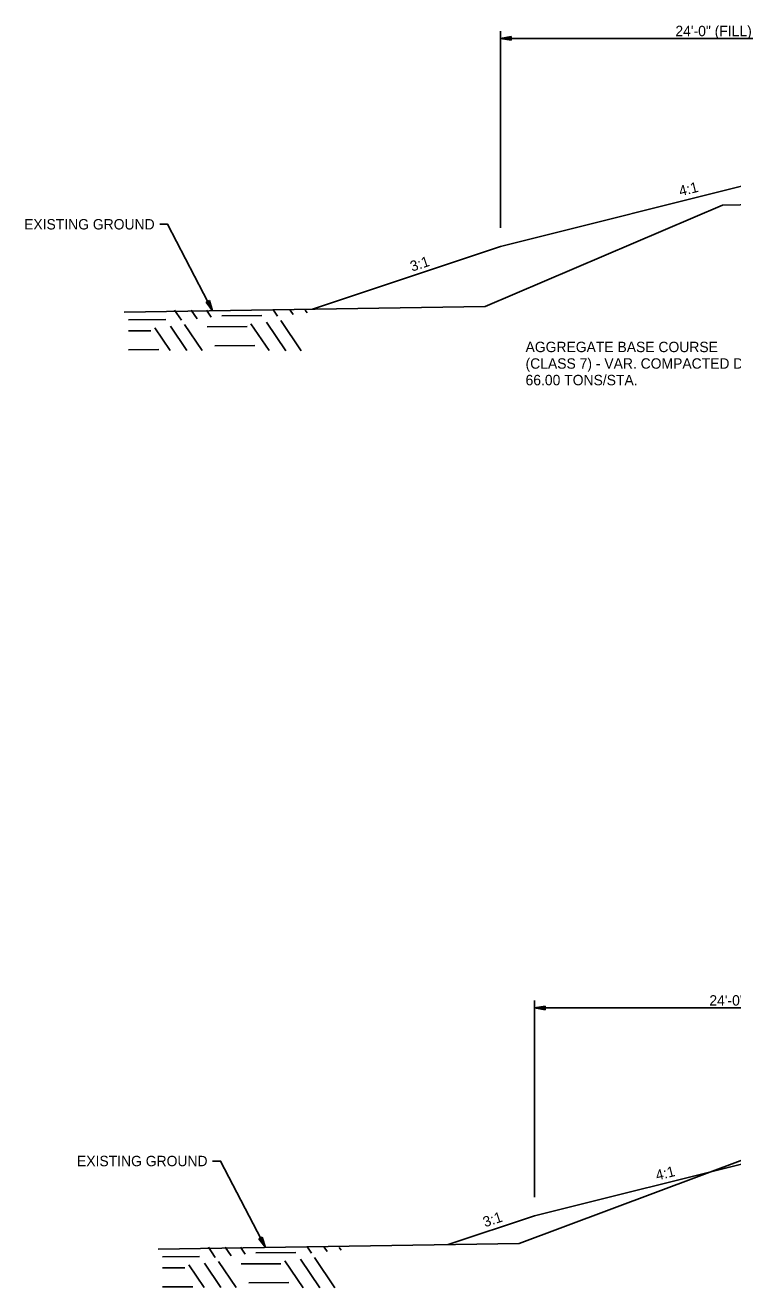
# Model space of a CAD drawing. Extents: x 1398183 to 1398373, y 1967240 to 1968889.
# Drawn here: x 1398185.5 to 1398225.6, y 1967722.3 to 1967793.9 of the extents above; entities that cross this region are included whole.
import ezdxf

# ---------------------------------------------------------------- set-up
doc = ezdxf.new("R2010")
doc.units = 0
for name, color, linetype in [('10', 7, 'Continuous'), ('19', 7, 'Continuous'), ('7', 7, 'Continuous'), ('9', 7, 'Continuous')]:
    doc.layers.add(name, color=color, linetype=linetype)

msp = doc.modelspace()

# ---------------------------------------------------------------- linework, layer by layer
at = {"layer": '19'}
for p, q in [((1398213.047, 1967793.262), (1398212.447, 1967793.157)), ((1398236.447, 1967793.157), (1398212.447, 1967793.157)), ((1398212.447, 1967793.157), (1398213.047, 1967793.052)), ((1398213.047, 1967793.207), (1398212.607, 1967793.172)), ((1398212.607, 1967793.142), (1398213.047, 1967793.102)), ((1398213.047, 1967793.052), (1398213.047, 1967793.262)), ((1398230.447, 1967785.854), (1398212.447, 1967781.354)), ((1398212.447, 1967781.354), (1398201.766, 1967777.793)), ((1398195.73, 1967778.19), (1398195.915, 1967778.286)), ((1398196.099, 1967777.706), (1398195.73, 1967778.19)), ((1398196.017, 1967777.842), (1398195.779, 1967778.211)), ((1398195.876, 1967778.262), (1398196.038, 1967777.856)), ((1398195.915, 1967778.286), (1398196.099, 1967777.706)), ((1398214.974, 1967738.244), (1398214.374, 1967738.139)), ((1398238.374, 1967738.139), (1398214.374, 1967738.139)), ((1398214.374, 1967738.139), (1398214.974, 1967738.034)), ((1398214.974, 1967738.189), (1398214.534, 1967738.154)), ((1398214.534, 1967738.124), (1398214.974, 1967738.084)), ((1398214.974, 1967738.034), (1398214.974, 1967738.244)), ((1398232.374, 1967730.836), (1398214.374, 1967726.336)), ((1398214.374, 1967726.336), (1398209.466, 1967724.7)), ((1398198.732, 1967725.025), (1398198.918, 1967725.121)), ((1398199.102, 1967724.541), (1398198.732, 1967725.025)), ((1398199.02, 1967724.677), (1398198.782, 1967725.045)), ((1398198.879, 1967725.097), (1398199.041, 1967724.691)), ((1398198.918, 1967725.121), (1398199.102, 1967724.541))]:
    msp.add_line(p, q, dxfattribs=at)
for points in [[(1398225.041, 1967783.694), (1398211.578, 1967777.944), (1398191.074, 1967777.629)], [(1398229.04, 1967783.774), (1398225.041, 1967783.694)], [(1398193.1, 1967782.612), (1398193.546, 1967782.612), (1398196.099, 1967777.706)], [(1398228.98, 1967730.552), (1398213.504, 1967724.762), (1398193.001, 1967724.447)], [(1398196.103, 1967729.447), (1398196.549, 1967729.447), (1398199.102, 1967724.541)]]:
    msp.add_lwpolyline(points, dxfattribs=at)
at = {"layer": '7'}
for p, q in [((1398212.447, 1967782.415), (1398212.447, 1967793.58)), ((1398214.374, 1967727.397), (1398214.373, 1967738.562))]:
    msp.add_line(p, q, dxfattribs=at)
at = {"layer": '9'}
for p, q in [((1398194.328, 1967777.162), (1398193.937, 1967777.743)), ((1398195.218, 1967777.253), (1398194.89, 1967777.741)), ((1398196.016, 1967777.344), (1398195.75, 1967777.74)), ((1398198.889, 1967777.432), (1398196.628, 1967777.418)), ((1398199.779, 1967777.394), (1398199.551, 1967777.733)), ((1398200.669, 1967777.485), (1398200.503, 1967777.732)), ((1398201.467, 1967777.576), (1398201.363, 1967777.73)), ((1398192.603, 1967776.571), (1398191.331, 1967776.563)), ((1398193.438, 1967777.201), (1398191.332, 1967777.187)), ((1398193.692, 1967775.449), (1398192.826, 1967776.738)), ((1398194.644, 1967775.447), (1398193.716, 1967776.829)), ((1398195.504, 1967775.446), (1398194.513, 1967776.92)), ((1398198.054, 1967776.803), (1398195.792, 1967776.788)), ((1398199.305, 1967775.439), (1398198.277, 1967776.97)), ((1398200.258, 1967775.438), (1398199.167, 1967777.061)), ((1398201.118, 1967775.436), (1398199.964, 1967777.152)), ((1398193.046, 1967775.495), (1398191.329, 1967775.484)), ((1398198.497, 1967775.727), (1398196.235, 1967775.712)), ((1398196.255, 1967723.98), (1398195.864, 1967724.561)), ((1398197.145, 1967724.071), (1398196.816, 1967724.559)), ((1398197.942, 1967724.163), (1398197.676, 1967724.558)), ((1398200.816, 1967724.25), (1398198.554, 1967724.236)), ((1398201.706, 1967724.212), (1398201.477, 1967724.551)), ((1398202.596, 1967724.303), (1398202.43, 1967724.55)), ((1398203.393, 1967724.394), (1398203.29, 1967724.548)), ((1398195.365, 1967724.019), (1398193.259, 1967724.005)), ((1398195.618, 1967722.267), (1398194.752, 1967723.556)), ((1398196.571, 1967722.266), (1398195.642, 1967723.647)), ((1398197.431, 1967722.264), (1398196.44, 1967723.739)), ((1398199.981, 1967723.621), (1398197.719, 1967723.606)), ((1398201.232, 1967722.258), (1398200.203, 1967723.788)), ((1398202.184, 1967722.256), (1398201.093, 1967723.879)), ((1398203.044, 1967722.254), (1398201.891, 1967723.97)), ((1398194.529, 1967723.389), (1398193.258, 1967723.381)), ((1398194.973, 1967722.313), (1398193.256, 1967722.302)), ((1398200.424, 1967722.545), (1398198.162, 1967722.53))]:
    msp.add_line(p, q, dxfattribs=at)

# ---------------------------------------------------------------- texts
at = {"layer": '10'}
for s, height, rotation, p in [('24\'-0" (FILL)', 0.59001, 0, (1398222.369, 1967793.286)), ('4:1', 0.59, 14.03624, (1398222.647, 1967784.196)), ('3:1', 0.59, 18.43495, (1398207.425, 1967779.918)), ('24\'-0" (FILL)', 0.59001, 0, (1398224.295, 1967738.268)), ('4:1', 0.59, 14.03624, (1398221.328, 1967728.337)), ('3:1', 0.59, 18.43495, (1398211.561, 1967725.682))]:
    msp.add_text(s, height=height, rotation=rotation, dxfattribs=at).set_placement(p)
for p in [(1398185.402, 1967782.317), (1398188.405, 1967729.152)]:
    msp.add_text('EXISTING GROUND', height=0.59001, dxfattribs=at).set_placement(p)
at = {"layer": '19'}
for s, p in [('AGGREGATE BASE COURSE', (1398213.863, 1967775.355)), ('(CLASS 7) - VAR. COMPACTED DEPTH', (1398213.863, 1967774.415)), ('66.00 TONS/STA.', (1398213.863, 1967773.475))]:
    msp.add_text(s, height=0.59001, rotation=360, dxfattribs=at).set_placement(p)

doc.saveas('drawing.dxf')
